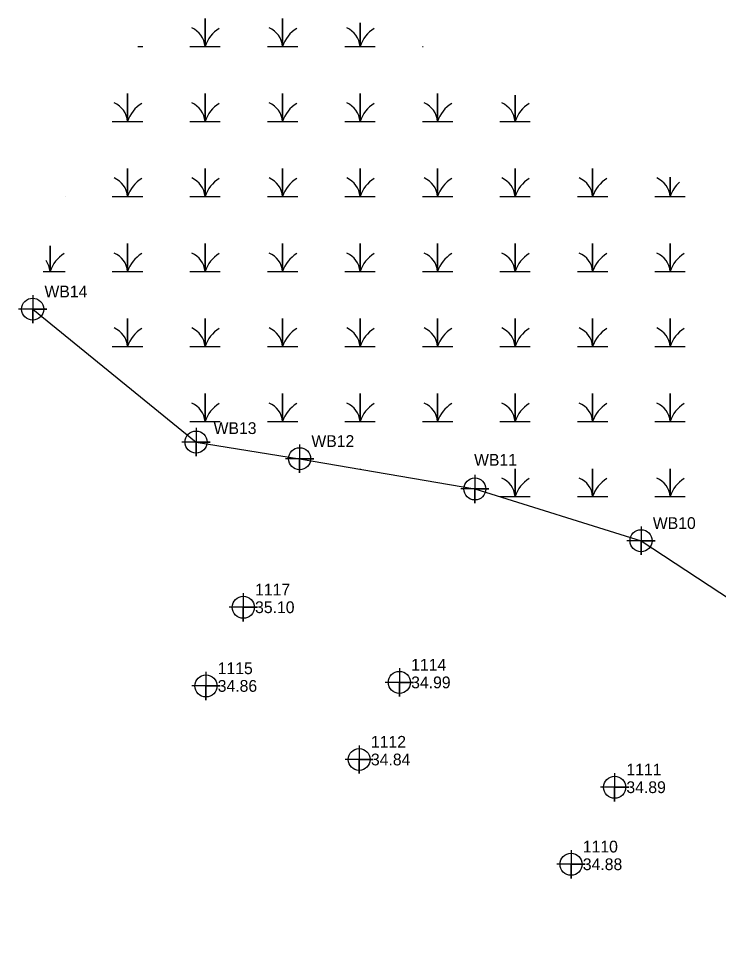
# Model space of a CAD drawing. Extents: x 2138832 to 2141061, y 149156 to 150675.
# Drawn here: x 2140217.7 to 2140366.3, y 149528.1 to 149725.2 of the extents above; entities that cross this region are included whole.
import ezdxf

# ---------------------------------------------------------------- set-up
doc = ezdxf.new("R2010")
doc.units = 0
for name, color, linetype in [('Exist Environmental Wetland Boundary', 7, 'Continuous'), ('Exist Environmental Wetland Boundary Cogo Number', 7, 'Continuous'), ('Exist Environmental Wetland Boundary Cogo Point CELL', 7, 'Continuous'), ('Exist Roads EOP Cogo Elevation', 7, 'Continuous'), ('Exist Roads EOP Cogo Number', 7, 'Continuous'), ('Exist Roads EOP Cogo Point CELL', 7, 'Continuous')]:
    doc.layers.add(name, color=color, linetype=linetype)

msp = doc.modelspace()

# ---------------------------------------------------------------- linework, layer by layer
at = {"layer": 'Exist Environmental Wetland Boundary'}
msp.add_lwpolyline([(2140220.74, 149663.51), (2140255.42, 149635.3), (2140277.39, 149631.77), (2140314.58, 149625.36), (2140349.86, 149614.36), (2140381.04, 149593.89), (2140416.32, 149561.58), (2140450.05, 149576.57), (2140474.9, 149577.61), (2140477.45, 149542.55), (2140488.03, 149517.58), (2140501.09, 149504.55), (2140539.61, 149485.41), (2140594.36, 149464.34)], dxfattribs=at)
at = {"layer": 'Exist Environmental Wetland Boundary Cogo Point CELL'}
for p, q in [((2140243.02, 149719.25), (2140244.09, 149719.25)), ((2140303.45, 149719.25), (2140303.62, 149719.25)), ((2140227.6, 149687.41), (2140227.64, 149687.41))]:
    msp.add_line(p, q, dxfattribs=at)
for points in [[(2140254.09, 149719.25), (2140257.32, 149719.25), (2140257.32, 149725.17), (2140257.32, 149719.25), (2140260.54, 149719.25)], [(2140270.54, 149719.25), (2140273.77, 149719.25), (2140273.77, 149725.17), (2140273.77, 149719.25), (2140277, 149719.25)], [(2140287, 149719.25), (2140290.22, 149719.25), (2140290.22, 149724.26)], [(2140290.22, 149724.26), (2140290.22, 149719.25), (2140293.45, 149719.25)], [(2140237.64, 149703.33), (2140240.87, 149703.33), (2140240.87, 149709.25), (2140240.87, 149703.33), (2140244.09, 149703.33)], [(2140254.09, 149703.33), (2140257.32, 149703.33), (2140257.32, 149709.25), (2140257.32, 149703.33), (2140260.54, 149703.33)], [(2140270.54, 149703.33), (2140273.77, 149703.33), (2140273.77, 149709.25), (2140273.77, 149703.33), (2140277, 149703.33)], [(2140287, 149703.33), (2140290.22, 149703.33), (2140290.22, 149709.25), (2140290.22, 149703.33), (2140293.45, 149703.33)], [(2140303.45, 149703.33), (2140306.67, 149703.33), (2140306.67, 149709.25), (2140306.67, 149703.33), (2140309.9, 149703.33)], [(2140319.9, 149703.33), (2140323.12, 149703.33), (2140323.12, 149708.92)], [(2140323.12, 149708.92), (2140323.12, 149703.33), (2140326.35, 149703.33)], [(2140237.64, 149687.41), (2140240.87, 149687.41), (2140240.87, 149693.33), (2140240.87, 149687.41), (2140244.09, 149687.41)], [(2140254.09, 149687.41), (2140257.32, 149687.41), (2140257.32, 149693.33), (2140257.32, 149687.41), (2140260.54, 149687.41)], [(2140270.54, 149687.41), (2140273.77, 149687.41), (2140273.77, 149693.33), (2140273.77, 149687.41), (2140277, 149687.41)], [(2140287, 149687.41), (2140290.22, 149687.41), (2140290.22, 149693.33), (2140290.22, 149687.41), (2140293.45, 149687.41)], [(2140303.45, 149687.41), (2140306.67, 149687.41), (2140306.67, 149693.33), (2140306.67, 149687.41), (2140309.9, 149687.41)], [(2140319.9, 149687.41), (2140323.12, 149687.41), (2140323.12, 149693.33), (2140323.12, 149687.41), (2140326.35, 149687.41)], [(2140336.35, 149687.41), (2140339.58, 149687.41), (2140339.58, 149693.33), (2140339.58, 149687.41), (2140342.8, 149687.41)], [(2140352.8, 149687.41), (2140356.03, 149687.41), (2140356.03, 149691.5)], [(2140356.03, 149691.5), (2140356.03, 149687.41), (2140359.25, 149687.41)], [(2140222.93, 149671.5), (2140224.42, 149671.5), (2140224.42, 149676.94)], [(2140224.42, 149676.94), (2140224.42, 149671.5), (2140227.64, 149671.5)], [(2140237.64, 149671.5), (2140240.87, 149671.5), (2140240.87, 149677.41), (2140240.87, 149671.5), (2140244.09, 149671.5)], [(2140254.09, 149671.5), (2140257.32, 149671.5), (2140257.32, 149677.41), (2140257.32, 149671.5), (2140260.54, 149671.5)], [(2140270.54, 149671.5), (2140273.77, 149671.5), (2140273.77, 149677.41), (2140273.77, 149671.5), (2140277, 149671.5)], [(2140287, 149671.5), (2140290.22, 149671.5), (2140290.22, 149677.41), (2140290.22, 149671.5), (2140293.45, 149671.5)], [(2140303.45, 149671.5), (2140306.67, 149671.5), (2140306.67, 149677.41), (2140306.67, 149671.5), (2140309.9, 149671.5)], [(2140319.9, 149671.5), (2140323.12, 149671.5), (2140323.12, 149677.41), (2140323.12, 149671.5), (2140326.35, 149671.5)], [(2140336.35, 149671.5), (2140339.58, 149671.5), (2140339.58, 149677.41), (2140339.58, 149671.5), (2140342.8, 149671.5)], [(2140352.8, 149671.5), (2140356.03, 149671.5), (2140356.03, 149677.41), (2140356.03, 149671.5), (2140359.25, 149671.5)], [(2140220.74, 149666.51), (2140220.74, 149660.51), (2140220.74, 149663.51), (2140223.74, 149663.51), (2140217.74, 149663.51)], [(2140237.64, 149655.58), (2140240.87, 149655.58), (2140240.87, 149661.5), (2140240.87, 149655.58), (2140244.09, 149655.58)], [(2140254.09, 149655.58), (2140257.32, 149655.58), (2140257.32, 149661.5), (2140257.32, 149655.58), (2140260.54, 149655.58)], [(2140270.54, 149655.58), (2140273.77, 149655.58), (2140273.77, 149661.5), (2140273.77, 149655.58), (2140277, 149655.58)], [(2140287, 149655.58), (2140290.22, 149655.58), (2140290.22, 149661.5), (2140290.22, 149655.58), (2140293.45, 149655.58)], [(2140303.45, 149655.58), (2140306.67, 149655.58), (2140306.67, 149661.5), (2140306.67, 149655.58), (2140309.9, 149655.58)], [(2140319.9, 149655.58), (2140323.12, 149655.58), (2140323.12, 149661.5), (2140323.12, 149655.58), (2140326.35, 149655.58)], [(2140336.35, 149655.58), (2140339.58, 149655.58), (2140339.58, 149661.5), (2140339.58, 149655.58), (2140342.8, 149655.58)], [(2140352.8, 149655.58), (2140356.03, 149655.58), (2140356.03, 149661.5), (2140356.03, 149655.58), (2140359.25, 149655.58)], [(2140254.09, 149639.66), (2140257.32, 149639.66), (2140257.32, 149645.58), (2140257.32, 149639.66), (2140260.54, 149639.66)], [(2140270.54, 149639.66), (2140273.77, 149639.66), (2140273.77, 149645.58), (2140273.77, 149639.66), (2140277, 149639.66)], [(2140287, 149639.66), (2140290.22, 149639.66), (2140290.22, 149645.58), (2140290.22, 149639.66), (2140293.45, 149639.66)], [(2140303.45, 149639.66), (2140306.67, 149639.66), (2140306.67, 149645.58), (2140306.67, 149639.66), (2140309.9, 149639.66)], [(2140319.9, 149639.66), (2140323.12, 149639.66), (2140323.12, 149645.58), (2140323.12, 149639.66), (2140326.35, 149639.66)], [(2140336.35, 149639.66), (2140339.58, 149639.66), (2140339.58, 149645.58), (2140339.58, 149639.66), (2140342.8, 149639.66)], [(2140352.8, 149639.66), (2140356.03, 149639.66), (2140356.03, 149645.58), (2140356.03, 149639.66), (2140359.25, 149639.66)], [(2140255.42, 149638.3), (2140255.42, 149632.3), (2140255.42, 149635.3), (2140258.42, 149635.3), (2140252.42, 149635.3)], [(2140277.39, 149634.77), (2140277.39, 149628.77), (2140277.39, 149631.77), (2140280.39, 149631.77), (2140274.39, 149631.77)], [(2140290.22, 149629.56), (2140290.22, 149629.66), (2140290.22, 149629.56)], [(2140319.9, 149623.74), (2140323.12, 149623.74), (2140323.12, 149629.66), (2140323.12, 149623.74), (2140326.35, 149623.74)], [(2140336.35, 149623.74), (2140339.58, 149623.74), (2140339.58, 149629.66), (2140339.58, 149623.74), (2140342.8, 149623.74)], [(2140352.8, 149623.74), (2140356.03, 149623.74), (2140356.03, 149629.66), (2140356.03, 149623.74), (2140359.25, 149623.74)], [(2140314.58, 149628.36), (2140314.58, 149622.36), (2140314.58, 149625.36), (2140317.58, 149625.36), (2140311.58, 149625.36)], [(2140349.86, 149617.36), (2140349.86, 149611.36), (2140349.86, 149614.36), (2140352.86, 149614.36), (2140346.86, 149614.36)]]:
    msp.add_lwpolyline(points, dxfattribs=at)
for centre in [(2140220.74, 149663.51), (2140255.42, 149635.3), (2140277.39, 149631.77), (2140314.58, 149625.36), (2140349.86, 149614.36)]:
    msp.add_circle(centre, 2.34, dxfattribs=at)
for centre, radius, start, end in [((2140252.72, 149718.92), 4.61, 4.1403, 67.535), ((2140269.17, 149718.92), 4.61, 4.1403, 67.535), ((2140285.62, 149718.92), 4.61, 4.1403, 67.535), ((2140264.16, 149716.98), 7.21, 122.1274, 161.6222), ((2140280.61, 149716.98), 7.21, 122.1274, 161.6222), ((2140297.06, 149716.98), 7.21, 122.1274, 161.6222), ((2140236.27, 149703), 4.61, 4.1403, 67.535), ((2140247.71, 149701.06), 7.21, 122.1274, 161.6222), ((2140252.72, 149703), 4.61, 4.1403, 67.535), ((2140264.16, 149701.06), 7.21, 122.1274, 161.6222), ((2140269.17, 149703), 4.61, 4.1403, 67.535), ((2140280.61, 149701.06), 7.21, 122.1274, 161.6222), ((2140285.62, 149703), 4.61, 4.1403, 67.535), ((2140297.06, 149701.06), 7.21, 122.1274, 161.6222), ((2140302.07, 149703), 4.61, 4.1403, 67.535), ((2140313.51, 149701.06), 7.21, 122.1274, 161.6222), ((2140318.52, 149703), 4.61, 4.1403, 67.535), ((2140329.96, 149701.06), 7.21, 122.1274, 161.6222), ((2140236.27, 149687.08), 4.61, 4.1403, 67.535), ((2140247.71, 149685.14), 7.21, 122.1274, 161.6222), ((2140252.72, 149687.08), 4.61, 4.1403, 67.535), ((2140264.16, 149685.14), 7.21, 122.1274, 161.6222), ((2140269.17, 149687.08), 4.61, 4.1403, 67.535), ((2140280.61, 149685.14), 7.21, 122.1274, 161.6222), ((2140285.62, 149687.08), 4.61, 4.1403, 67.535), ((2140297.06, 149685.14), 7.21, 122.1274, 161.6222), ((2140302.07, 149687.08), 4.61, 4.1403, 67.535), ((2140313.51, 149685.14), 7.21, 122.1274, 161.6222), ((2140318.52, 149687.08), 4.61, 4.1403, 67.535), ((2140329.96, 149685.14), 7.21, 122.1274, 161.6222), ((2140334.98, 149687.08), 4.61, 4.1403, 67.535), ((2140346.42, 149685.14), 7.21, 122.1274, 161.6222), ((2140351.43, 149687.08), 4.61, 4.1403, 67.535), ((2140362.87, 149685.14), 7.21, 132.4833, 161.6222), ((2140231.26, 149669.22), 7.21, 122.1274, 161.6222), ((2140236.27, 149671.16), 4.61, 4.1403, 67.535), ((2140247.71, 149669.22), 7.21, 122.1274, 161.6222), ((2140252.72, 149671.16), 4.61, 4.1403, 67.535), ((2140264.16, 149669.22), 7.21, 122.1274, 161.6222), ((2140269.17, 149671.16), 4.61, 4.1403, 67.535), ((2140280.61, 149669.22), 7.21, 122.1274, 161.6222), ((2140285.62, 149671.16), 4.61, 4.1403, 67.535), ((2140297.06, 149669.22), 7.21, 122.1274, 161.6222), ((2140302.07, 149671.16), 4.61, 4.1403, 67.535), ((2140313.51, 149669.22), 7.21, 122.1274, 161.6222), ((2140318.52, 149671.16), 4.61, 4.1403, 67.535), ((2140329.96, 149669.22), 7.21, 122.1274, 161.6222), ((2140334.98, 149671.16), 4.61, 4.1403, 67.535), ((2140346.42, 149669.22), 7.21, 122.1274, 161.6222), ((2140351.43, 149671.16), 4.61, 4.1403, 67.535), ((2140362.87, 149669.22), 7.21, 122.1274, 161.6222), ((2140219.82, 149671.16), 4.61, 4.1403, 35.5252), ((2140236.27, 149655.25), 4.61, 4.1403, 67.535), ((2140247.71, 149653.31), 7.21, 122.1274, 161.6222), ((2140252.72, 149655.25), 4.61, 4.1403, 67.535), ((2140264.16, 149653.31), 7.21, 122.1274, 161.6222), ((2140269.17, 149655.25), 4.61, 4.1403, 67.535), ((2140280.61, 149653.31), 7.21, 122.1274, 161.6222), ((2140285.62, 149655.25), 4.61, 4.1403, 67.535), ((2140297.06, 149653.31), 7.21, 122.1274, 161.6222), ((2140302.07, 149655.25), 4.61, 4.1403, 67.535), ((2140313.51, 149653.31), 7.21, 122.1274, 161.6222), ((2140318.52, 149655.25), 4.61, 4.1403, 67.535), ((2140329.96, 149653.31), 7.21, 122.1274, 161.6222), ((2140334.98, 149655.25), 4.61, 4.1403, 67.535), ((2140346.42, 149653.31), 7.21, 122.1274, 161.6222), ((2140351.43, 149655.25), 4.61, 4.1403, 67.535), ((2140362.87, 149653.31), 7.21, 122.1274, 161.6222), ((2140252.72, 149639.33), 4.61, 4.1403, 67.535), ((2140264.16, 149637.39), 7.21, 122.1274, 161.6222), ((2140269.17, 149639.33), 4.61, 4.1403, 67.535), ((2140280.61, 149637.39), 7.21, 122.1274, 161.6222), ((2140285.62, 149639.33), 4.61, 4.1403, 67.535), ((2140297.06, 149637.39), 7.21, 122.1274, 161.6222), ((2140302.07, 149639.33), 4.61, 4.1403, 67.535), ((2140313.51, 149637.39), 7.21, 122.1274, 161.6222), ((2140318.52, 149639.33), 4.61, 4.1403, 67.535), ((2140329.96, 149637.39), 7.21, 122.1274, 161.6222), ((2140334.98, 149639.33), 4.61, 4.1403, 67.535), ((2140346.42, 149637.39), 7.21, 122.1274, 161.6222), ((2140351.43, 149639.33), 4.61, 4.1403, 67.535), ((2140362.87, 149637.39), 7.21, 122.1274, 161.6222), ((2140318.52, 149623.41), 4.61, 4.1403, 67.535), ((2140329.96, 149621.47), 7.21, 122.1274, 161.6222), ((2140334.98, 149623.41), 4.61, 4.1403, 67.535), ((2140346.42, 149621.47), 7.21, 122.1274, 161.6222), ((2140351.43, 149623.41), 4.61, 4.1403, 67.535), ((2140362.87, 149621.47), 7.21, 122.1274, 161.6222)]:
    msp.add_arc(centre, radius, start, end, dxfattribs=at)
at = {"layer": 'Exist Roads EOP Cogo Point CELL'}
for points in [[(2140265.44, 149603.26), (2140265.44, 149597.26), (2140265.44, 149600.26), (2140268.44, 149600.26), (2140262.44, 149600.26)], [(2140298.57, 149587.31), (2140298.57, 149581.31), (2140298.57, 149584.31), (2140301.57, 149584.31), (2140295.57, 149584.31)], [(2140257.51, 149586.56), (2140257.51, 149580.56), (2140257.51, 149583.56), (2140260.51, 149583.56), (2140254.51, 149583.56)], [(2140290.03, 149570.95), (2140290.03, 149564.95), (2140290.03, 149567.95), (2140293.03, 149567.95), (2140287.03, 149567.95)], [(2140344.25, 149565.07), (2140344.25, 149559.07), (2140344.25, 149562.07), (2140347.25, 149562.07), (2140341.25, 149562.07)], [(2140335, 149548.72), (2140335, 149542.72), (2140335, 149545.72), (2140338, 149545.72), (2140332, 149545.72)]]:
    msp.add_lwpolyline(points, dxfattribs=at)
for centre in [(2140265.44, 149600.26), (2140257.51, 149583.56), (2140298.57, 149584.31), (2140290.03, 149567.95), (2140344.25, 149562.07), (2140335, 149545.72)]:
    msp.add_circle(centre, 2.34, dxfattribs=at)

# ---------------------------------------------------------------- texts
at = {"layer": 'Exist Environmental Wetland Boundary Cogo Number'}
for s, p in [('WB14', (2140223.24, 149666.01)), ('WB13', (2140259.14, 149637.01)), ('WB12', (2140279.89, 149634.27)), ('WB11', (2140314.42, 149630.28)), ('WB10', (2140352.36, 149616.86))]:
    msp.add_text(s, height=2.5, dxfattribs=at).set_placement(p)
at = {"layer": 'Exist Roads EOP Cogo Elevation'}
for s, p in [('35.10', (2140267.94, 149599.01)), ('34.99', (2140301.07, 149583.06)), ('34.86', (2140260.01, 149582.31)), ('34.84', (2140292.53, 149566.7)), ('34.89', (2140346.75, 149560.82)), ('34.88', (2140337.5, 149544.47))]:
    msp.add_text(s, height=2.5, dxfattribs=at).set_placement(p)
at = {"layer": 'Exist Roads EOP Cogo Number'}
for s, p in [('1117', (2140267.94, 149602.76)), ('1114', (2140301.07, 149586.81)), ('1115', (2140260.01, 149586.06)), ('1112', (2140292.53, 149570.45)), ('1111', (2140346.75, 149564.57)), ('1110', (2140337.5, 149548.22))]:
    msp.add_text(s, height=2.5, dxfattribs=at).set_placement(p)

doc.saveas('drawing.dxf')
